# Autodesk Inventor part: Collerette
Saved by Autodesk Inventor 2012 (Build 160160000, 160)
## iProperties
Created: 2013-08
Part Number: Collerette
Material: Default
Document SubType Name: Modeling
Designer: hilarion
Density: 1 g/cm^3
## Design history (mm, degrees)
node "Collerette1"
node "Collerette"
node "Base1"
